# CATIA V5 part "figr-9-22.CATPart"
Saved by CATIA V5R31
Part number: Part3
Bounding box of the stored display mesh (mm): x -112 to 0, y -101.683 to 103.294, z -80.304 to 44.415
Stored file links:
  D:\PROJECTS\Project 2021\US EDITION\CATIA V5 6R 2021\Resources\Part Files\c09_catia_v5_6r2021_prt\c09_catia_v5_6r2021_prt\figr-9-22.CATPart
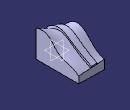
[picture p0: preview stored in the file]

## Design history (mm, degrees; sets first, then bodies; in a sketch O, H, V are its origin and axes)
Set1
  Plane1: type Offset, RefPlane yz-plane, Offset -112
  Plane2: type Offset, RefPlane yz-plane, Offset -63
  Plane3: type Normal, Curve Sketch4, RefPoint vertex of Sketch4
Body1 (main body)
  Sketch1 on yz-plane, origin (0, 0, 0), H (0, 1, 0), V (0, 0, 1)
    spline S1 through (-92.6897, 40.1119) (-30, 30) (10, -10) (60, -30) (97.3103, -50.3041)
    line L1 (97.3103, -50.3041) -> (97.3103, -80.3041)
    line L2 (97.3103, -80.3041) -> (-92.6897, -80.3041)
    line L3 (-92.6897, -80.3041) -> (-92.6897, 40.1119)
    point P3 (-92.6897, 40.1119)
    point P4 (97.3103, -50.3041)
    point P5 (-92.6897, 40.1119)
    point P6 (97.3103, -50.3041)
    vertical: L1 V, L3 V
    horizontal: L2 H
    coincidence: P5 P3, P6 P4
  Sketch2 on Plane1, origin (-112, 0, 0), H (0, 1, 0), V (0, 0, 1)
    spline S1 through (-90, -30) (-70, 10) (-20, 40) (40, 0) (100, -40)
    line L1 (100, -40) -> (100, -80)
    line L2 (100, -80) -> (-90, -80)
    line L3 (-90, -80) -> (-90, -30)
    point P3 (-90, -30)
    point P4 (100, -40)
    point P5 (40, 0)
    point P6 (-90, -30)
    point P7 (100, -40)
    coincidence: P5 H, P6 P3, P7 P4
    vertical: L1 V, L3 V
    horizontal: L2 H
  Loft1: Sections (Sketch1; Sketch2)
  Sketch3 on Plane3, origin (0, -40.1726, -44.9298), H (1, 0, 0), V (0, -0.7455, 0.6665)
    point P1 (-63, 68.4187)
    line L1 (-63, 68.4187) -> (-75.2117, 62.4925)
    line L2 (-75.2117, 62.4925) -> (-79.6266, 71.5898)
    line L3 (-79.6266, 71.5898) -> (-57.1205, 82.5119)
    line L4 (-57.1205, 82.5119) -> (-52.7056, 73.4145)
    point P5 (-52.7056, 73.4145)
    line L5 (-52.7056, 73.4145) -> (-63, 68.4187)
    reference projected point E1 (-63, 68.4187) from vertex of Sketch4
    perpendicularity: L2 L1
    parallelism: L3 L1, L4 L2, L5 L1
    coincidence: P5 L1, P1 E1
  Sketch4 on Plane2, origin (-63, 0, 0), H (0, 1, 0), V (0, 0, 1)
    intersected curve E1 from face of Loft1
  Rib1: profile Sketch3, centre curve Sketch4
